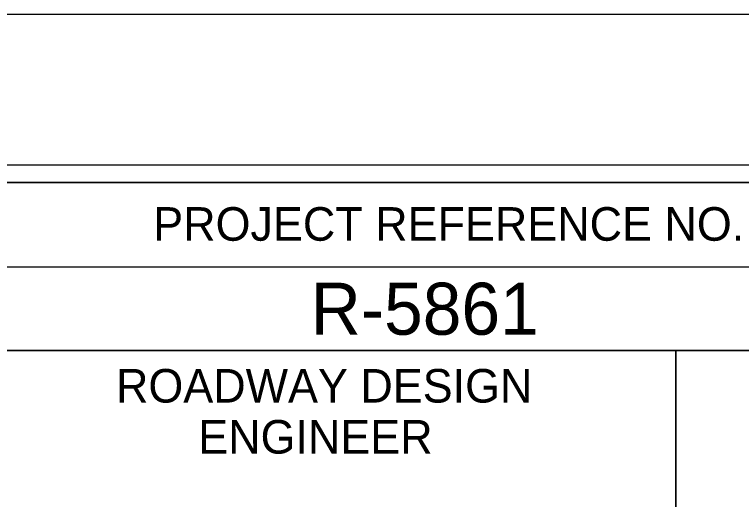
# Model space of a CAD drawing. Extents: x 497599 to 513368, y 404140 to 476034.
# Drawn here: x 507160.2 to 507268.5, y 439788.9 to 439861.1 of the extents above; entities that cross this region are included whole.
import ezdxf

# ---------------------------------------------------------------- set-up
doc = ezdxf.new("R2010")
doc.units = 0
for name, color, linetype in [('Sheet Cutting Line CELL', 7, 'Continuous'), ('Sheet Data Field CELL', 7, 'Continuous'), ('Sheet Plot Border Inside CELL', 7, 'Continuous'), ('Sheet Plot Border Outside CELL', 7, 'Continuous'), ('Sheet Profile CELL', 7, 'Continuous'), ('Sheet Profile Grid Major CELL', 7, 'Continuous'), ('Sheet Profile Grid Minor CELL', 7, 'Continuous')]:
    doc.layers.add(name, color=color, linetype=linetype)

msp = doc.modelspace()

# ---------------------------------------------------------------- linework, layer by layer
at = {"layer": 'Sheet Cutting Line CELL'}
msp.add_line((507375.68, 439861.14), (505691.68, 439861.14), dxfattribs=at)
at = {"layer": 'Sheet Plot Border Inside CELL'}
msp.add_lwpolyline([(505704.68, 438783.59), (507371.18, 438783.59), (507371.18, 439838.69), (505704.68, 439838.69)], close=True, dxfattribs=at)
at = {"layer": 'Sheet Plot Border Outside CELL'}
msp.add_lwpolyline([(505691.68, 438761.14), (507375.68, 438761.14), (507375.68, 439861.14), (505691.68, 439861.14)], close=True, dxfattribs=at)
at = {"layer": 'Sheet Profile CELL'}
for p, q in [((507158.63, 439823.59), (507358.68, 439823.59)), ((507258.68, 439811.09), (507258.68, 439698.64))]:
    msp.add_line(p, q, dxfattribs=at)
for points in [[(507358.68, 439836.14), (505858.68, 439836.14), (505858.68, 438786.14), (507358.68, 438786.14)], [(507158.63, 439836.14), (507358.68, 439836.14), (507358.68, 439811.09), (507158.63, 439811.09)], [(507158.63, 439811.09), (507258.68, 439811.09), (507258.68, 439698.59), (507158.63, 439698.59)], [(507258.68, 439811.09), (507358.68, 439811.09), (507358.68, 439698.59), (507258.68, 439698.59)]]:
    msp.add_lwpolyline(points, close=True, dxfattribs=at)
at = {"layer": 'Sheet Profile Grid Major CELL'}
msp.add_lwpolyline([(506708.68, 439336.14), (506758.68, 439336.14), (506758.68, 439836.14), (506808.68, 439836.14), (506808.68, 439336.14), (506858.68, 439336.14), (506858.68, 439836.14), (506908.68, 439836.14), (506908.68, 439336.14), (506958.68, 439336.14), (506958.68, 439836.14), (507008.68, 439836.14), (507008.68, 439336.14), (507058.68, 439336.14), (507058.68, 439836.14), (507108.68, 439836.14), (507108.68, 439336.14), (507158.68, 439336.14), (507158.68, 439836.14), (507184.98, 439836.14)], dxfattribs=at)
at = {"layer": 'Sheet Profile Grid Minor CELL'}
msp.add_lwpolyline([(507153.68, 439836.14), (507163.68, 439836.14)], dxfattribs=at)

# ---------------------------------------------------------------- texts
at = {"layer": 'Sheet Data Field CELL'}
msp.add_text('R-5861', height=7.75, dxfattribs=at).set_placement((507204.29, 439813.46))
at = {"layer": 'Sheet Profile CELL'}
for s, height, p in [('PROJECT REFERENCE NO.', 5.0001, (507180.84, 439827.46)), ('ROADWAY DESIGN', 5.0001, (507175.29, 439803.36)), ('ENGINEER', 5, (507187.54, 439795.76))]:
    msp.add_text(s, height=height, dxfattribs=at).set_placement(p)

doc.saveas('drawing.dxf')
